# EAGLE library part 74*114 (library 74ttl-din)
Dual J-K negative edge triggered FLIP FLOP, preset, common clear, clock
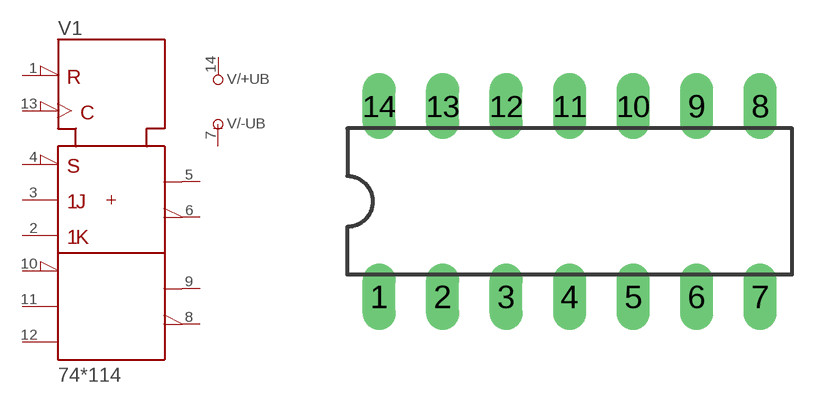
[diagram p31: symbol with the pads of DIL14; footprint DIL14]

Designator prefix V; gates /+UB=+UB /-UB=-UB 1=114

## 74114N  [DIL14]
1  1:CLR\  in
2  1:1K  in
3  1:1J  in
4  1:1PRE\  in
5  1:1Q  out
6  1:1Q\  out
7  /-UB:-UB  pwr
8  1:2Q\  out
9  1:2Q  out
10  1:2PRE\  in
11  1:2J  in
12  1:2K  in
13  1:CLK  in
14  /+UB:+UB  pwr

## Footprint DIL14 (pad centres in mm)
Dual In Line Package
drill 0.813 long: 1 -7.62,-3.81; 2 -5.08,-3.81; 3 -2.54,-3.81; 4 0,-3.81; 5 2.54,-3.81; 6 5.08,-3.81; 7 7.62,-3.81; 8 7.62,3.81; 9 5.08,3.81; 10 2.54,3.81; 11 0,3.81; 12 -2.54,3.81; 13 -5.08,3.81; 14 -7.62,3.81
